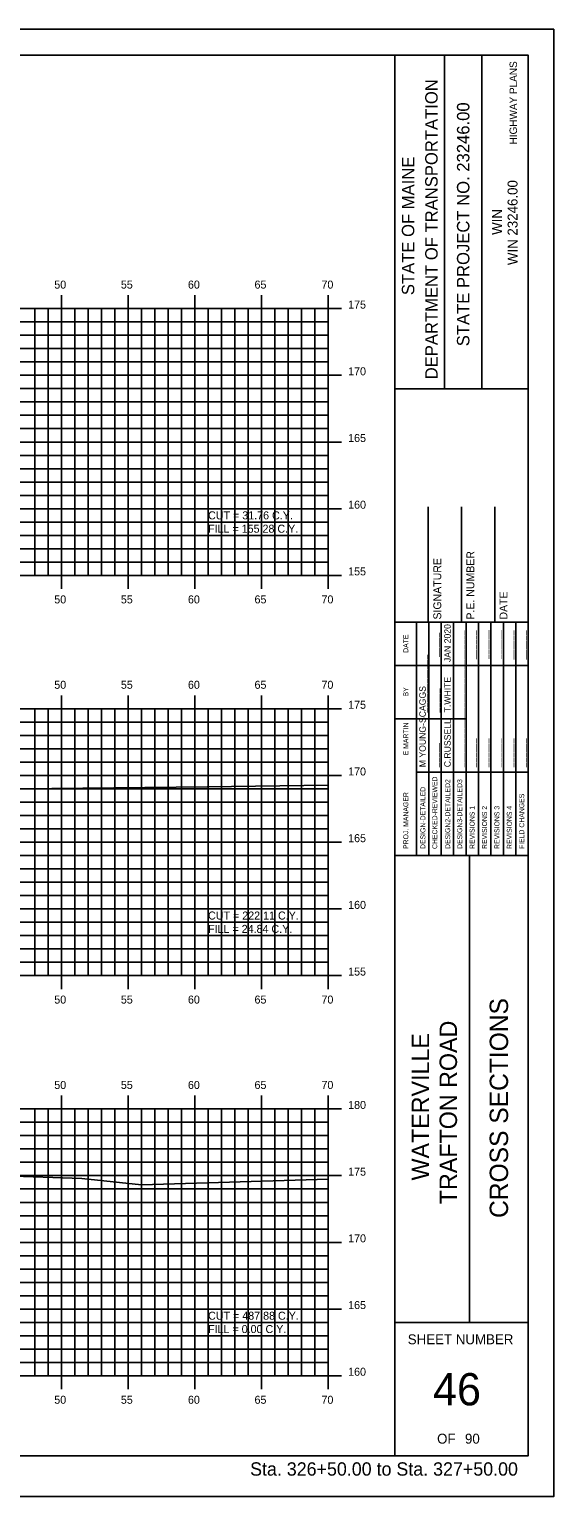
# Model space of a CAD drawing. Extents: x 1140759 to 1140929, y 608981 to 609091.
# Drawn here: x 1140889.6 to 1140928.9, y 608981.3 to 609091.3 of the extents above; entities that cross this region are included whole.
import ezdxf

# ---------------------------------------------------------------- set-up
doc = ezdxf.new("R2010")
doc.units = 0
for name, color, linetype in [('BORDER', 7, 'Continuous'), ('D_Text_Standard', 7, 'Continuous'), ('H_V ANNOTATION', 7, 'Continuous'), ('HIGHWAY_TITLE', 7, 'Continuous'), ('MAJOR', 7, 'Continuous'), ('MINOR', 7, 'Continuous'), ('PLOT BOUNDARY', 7, 'Continuous'), ('S_Roadway_Centerline', 7, 'Continuous')]:
    doc.layers.add(name, color=color, linetype=linetype)

msp = doc.modelspace()

# ---------------------------------------------------------------- linework, layer by layer
at = {"layer": 'BORDER'}
for p, q in [((1140917, 608984.34), (1140917, 609089.34)), ((1140920.73, 609064.33), (1140920.73, 609089.33)), ((1140923.52, 609064.33), (1140923.52, 609089.33)), ((1140917, 609064.33), (1140927, 609064.33)), ((1140919.5, 609046.84), (1140919.5, 609055.49)), ((1140922, 609046.84), (1140922, 609055.49)), ((1140924.5, 609046.84), (1140924.5, 609055.49)), ((1140917, 609046.84), (1140927, 609046.84)), ((1140917, 609029.34), (1140927, 609029.34)), ((1140922.59, 608994.34), (1140922.59, 609029.34)), ((1140917, 608994.34), (1140927, 608994.34))]:
    msp.add_line(p, q, dxfattribs=at)
msp.add_lwpolyline([(1140767, 608984.34), (1140927, 608984.34), (1140927, 609089.34), (1140767, 609089.34)], close=True, dxfattribs=at)
for points in [[(1140918.62, 609043.59), (1140918.62, 609046.84)], [(1140918.62, 609029.34), (1140918.62, 609046.13)], [(1140919.55, 609029.34), (1140919.55, 609046.84)], [(1140920.48, 609046.84), (1140920.48, 609029.34)], [(1140921.41, 609029.34), (1140921.41, 609046.84)], [(1140922.34, 609029.34), (1140922.34, 609046.84)], [(1140923.28, 609029.34), (1140923.28, 609046.84)], [(1140924.21, 609029.34), (1140924.21, 609046.84)], [(1140925.14, 609029.34), (1140925.14, 609046.84)], [(1140926.07, 609029.34), (1140926.07, 609046.84)], [(1140917, 609043.59), (1140927, 609043.59)], [(1140917, 609039.59), (1140918.62, 609039.59)], [(1140918.62, 609039.59), (1140922.34, 609039.59)], [(1140918.62, 609035.59), (1140927, 609035.59)]]:
    msp.add_lwpolyline(points, dxfattribs=at)
at = {"layer": 'MAJOR'}
for p, q in [((1140892, 609071.34), (1140892, 609070.34)), ((1140897, 609071.34), (1140897, 609070.34)), ((1140902, 609071.34), (1140902, 609070.34)), ((1140907, 609071.34), (1140907, 609070.34)), ((1140912, 609071.34), (1140912, 609070.34)), ((1140772, 609070.34), (1140912, 609070.34)), ((1140772, 609070.34), (1140912, 609070.34)), ((1140892, 609050.34), (1140892, 609070.34)), ((1140897, 609050.34), (1140897, 609070.34)), ((1140902, 609050.34), (1140902, 609070.34)), ((1140907, 609050.34), (1140907, 609070.34)), ((1140913, 609070.34), (1140911, 609070.34)), ((1140912, 609050.34), (1140912, 609070.34)), ((1140912, 609050.34), (1140912, 609070.34)), ((1140772, 609065.34), (1140912, 609065.34)), ((1140913, 609065.34), (1140911, 609065.34)), ((1140772, 609060.34), (1140912, 609060.34)), ((1140913, 609060.34), (1140911, 609060.34)), ((1140772, 609055.34), (1140912, 609055.34)), ((1140913, 609055.34), (1140911, 609055.34)), ((1140772, 609050.34), (1140912, 609050.34)), ((1140772, 609050.34), (1140912, 609050.34)), ((1140892, 609049.33), (1140892, 609050.34)), ((1140897, 609049.33), (1140897, 609050.34)), ((1140902, 609049.33), (1140902, 609050.34)), ((1140907, 609049.33), (1140907, 609050.34)), ((1140913, 609050.34), (1140911, 609050.34)), ((1140912, 609049.33), (1140912, 609050.34)), ((1140772, 609040.34), (1140912, 609040.34)), ((1140772, 609040.34), (1140912, 609040.34)), ((1140892, 609041.34), (1140892, 609040.34)), ((1140892, 609020.34), (1140892, 609040.34)), ((1140897, 609041.34), (1140897, 609040.34)), ((1140897, 609020.34), (1140897, 609040.34)), ((1140902, 609041.34), (1140902, 609040.34)), ((1140902, 609020.34), (1140902, 609040.34)), ((1140907, 609041.34), (1140907, 609040.34)), ((1140907, 609020.34), (1140907, 609040.34)), ((1140913, 609040.34), (1140911, 609040.34)), ((1140912, 609041.34), (1140912, 609040.34)), ((1140912, 609020.34), (1140912, 609040.34)), ((1140912, 609020.34), (1140912, 609040.34)), ((1140772, 609035.34), (1140912, 609035.34)), ((1140913, 609035.34), (1140911, 609035.34)), ((1140772, 609030.34), (1140912, 609030.34)), ((1140913, 609030.34), (1140911, 609030.34)), ((1140772, 609025.34), (1140912, 609025.34)), ((1140913, 609025.34), (1140911, 609025.34)), ((1140772, 609020.34), (1140912, 609020.34)), ((1140772, 609020.34), (1140912, 609020.34)), ((1140892, 609019.33), (1140892, 609020.34)), ((1140897, 609019.33), (1140897, 609020.34)), ((1140902, 609019.33), (1140902, 609020.34)), ((1140907, 609019.33), (1140907, 609020.34)), ((1140913, 609020.34), (1140911, 609020.34)), ((1140912, 609019.33), (1140912, 609020.34)), ((1140892, 609011.34), (1140892, 609010.34)), ((1140897, 609011.34), (1140897, 609010.34)), ((1140902, 609011.34), (1140902, 609010.34)), ((1140907, 609011.34), (1140907, 609010.34)), ((1140912, 609011.34), (1140912, 609010.34)), ((1140772, 609010.34), (1140912, 609010.34)), ((1140772, 609010.34), (1140912, 609010.34)), ((1140892, 608990.34), (1140892, 609010.34)), ((1140897, 608990.34), (1140897, 609010.34)), ((1140902, 608990.34), (1140902, 609010.34)), ((1140907, 608990.34), (1140907, 609010.34)), ((1140913, 609010.34), (1140911, 609010.34)), ((1140912, 608990.34), (1140912, 609010.34)), ((1140912, 608990.34), (1140912, 609010.34)), ((1140772, 609005.34), (1140912, 609005.34)), ((1140913, 609005.34), (1140911, 609005.34)), ((1140772, 609000.34), (1140912, 609000.34)), ((1140913, 609000.34), (1140911, 609000.34)), ((1140772, 608995.34), (1140912, 608995.34)), ((1140913, 608995.34), (1140911, 608995.34)), ((1140772, 608990.34), (1140912, 608990.34)), ((1140772, 608990.34), (1140912, 608990.34)), ((1140892, 608989.33), (1140892, 608990.34)), ((1140897, 608989.33), (1140897, 608990.34)), ((1140902, 608989.33), (1140902, 608990.34)), ((1140907, 608989.33), (1140907, 608990.34)), ((1140913, 608990.34), (1140911, 608990.34)), ((1140912, 608989.33), (1140912, 608990.34))]:
    msp.add_line(p, q, dxfattribs=at)
at = {"layer": 'MINOR'}
for p, q in [((1140890, 609050.34), (1140890, 609070.34)), ((1140891, 609050.34), (1140891, 609070.34)), ((1140893, 609050.34), (1140893, 609070.34)), ((1140894, 609050.34), (1140894, 609070.34)), ((1140895, 609050.34), (1140895, 609070.34)), ((1140896, 609050.34), (1140896, 609070.34)), ((1140898, 609050.34), (1140898, 609070.34)), ((1140899, 609050.34), (1140899, 609070.34)), ((1140900, 609050.34), (1140900, 609070.34)), ((1140901, 609050.34), (1140901, 609070.34)), ((1140903, 609050.34), (1140903, 609070.34)), ((1140904, 609050.34), (1140904, 609070.34)), ((1140905, 609050.34), (1140905, 609070.34)), ((1140906, 609050.34), (1140906, 609070.34)), ((1140908, 609050.34), (1140908, 609070.34)), ((1140909, 609050.34), (1140909, 609070.34)), ((1140910, 609050.34), (1140910, 609070.34)), ((1140911, 609050.34), (1140911, 609070.34)), ((1140772, 609069.34), (1140912, 609069.34)), ((1140912, 609069.34), (1140911, 609069.34)), ((1140772, 609068.34), (1140912, 609068.34)), ((1140912, 609068.34), (1140911, 609068.34)), ((1140772, 609067.34), (1140912, 609067.34)), ((1140912, 609067.34), (1140911, 609067.34)), ((1140772, 609066.34), (1140912, 609066.34)), ((1140912, 609066.34), (1140911, 609066.34)), ((1140772, 609064.34), (1140912, 609064.34)), ((1140912, 609064.34), (1140911, 609064.34)), ((1140772, 609063.34), (1140912, 609063.34)), ((1140772, 609062.34), (1140912, 609062.34)), ((1140912, 609063.34), (1140911, 609063.34)), ((1140912, 609062.34), (1140911, 609062.34)), ((1140772, 609061.34), (1140912, 609061.34)), ((1140912, 609061.34), (1140911, 609061.34)), ((1140772, 609059.34), (1140912, 609059.34)), ((1140912, 609059.34), (1140911, 609059.34)), ((1140772, 609058.34), (1140912, 609058.34)), ((1140912, 609058.34), (1140911, 609058.34)), ((1140772, 609057.34), (1140912, 609057.34)), ((1140912, 609057.34), (1140911, 609057.34)), ((1140772, 609056.34), (1140912, 609056.34)), ((1140912, 609056.34), (1140911, 609056.34)), ((1140772, 609054.34), (1140912, 609054.34)), ((1140912, 609054.34), (1140911, 609054.34)), ((1140772, 609053.34), (1140912, 609053.34)), ((1140912, 609053.34), (1140911, 609053.34)), ((1140772, 609052.34), (1140912, 609052.34)), ((1140772, 609051.34), (1140912, 609051.34)), ((1140912, 609052.34), (1140911, 609052.34)), ((1140912, 609051.34), (1140911, 609051.34)), ((1140890, 609020.34), (1140890, 609040.34)), ((1140891, 609020.34), (1140891, 609040.34)), ((1140893, 609020.34), (1140893, 609040.34)), ((1140894, 609020.34), (1140894, 609040.34)), ((1140895, 609020.34), (1140895, 609040.34)), ((1140896, 609020.34), (1140896, 609040.34)), ((1140898, 609020.34), (1140898, 609040.34)), ((1140899, 609020.34), (1140899, 609040.34)), ((1140900, 609020.34), (1140900, 609040.34)), ((1140901, 609020.34), (1140901, 609040.34)), ((1140903, 609020.34), (1140903, 609040.34)), ((1140904, 609020.34), (1140904, 609040.34)), ((1140905, 609020.34), (1140905, 609040.34)), ((1140906, 609020.34), (1140906, 609040.34)), ((1140908, 609020.34), (1140908, 609040.34)), ((1140909, 609020.34), (1140909, 609040.34)), ((1140910, 609020.34), (1140910, 609040.34)), ((1140911, 609020.34), (1140911, 609040.34)), ((1140772, 609039.34), (1140912, 609039.34)), ((1140912, 609039.34), (1140911, 609039.34)), ((1140772, 609038.34), (1140912, 609038.34)), ((1140912, 609038.34), (1140911, 609038.34)), ((1140772, 609037.34), (1140912, 609037.34)), ((1140912, 609037.34), (1140911, 609037.34)), ((1140772, 609036.34), (1140912, 609036.34)), ((1140912, 609036.34), (1140911, 609036.34)), ((1140772, 609034.34), (1140912, 609034.34)), ((1140912, 609034.34), (1140911, 609034.34)), ((1140772, 609033.34), (1140912, 609033.34)), ((1140912, 609033.34), (1140911, 609033.34)), ((1140772, 609032.34), (1140912, 609032.34)), ((1140912, 609032.34), (1140911, 609032.34)), ((1140772, 609031.34), (1140912, 609031.34)), ((1140912, 609031.34), (1140911, 609031.34)), ((1140772, 609029.34), (1140912, 609029.34)), ((1140912, 609029.34), (1140911, 609029.34)), ((1140772, 609028.34), (1140912, 609028.34)), ((1140912, 609028.34), (1140911, 609028.34)), ((1140772, 609027.34), (1140912, 609027.34)), ((1140912, 609027.34), (1140911, 609027.34)), ((1140772, 609026.34), (1140912, 609026.34)), ((1140912, 609026.34), (1140911, 609026.34)), ((1140772, 609024.34), (1140912, 609024.34)), ((1140912, 609024.34), (1140911, 609024.34)), ((1140772, 609023.34), (1140912, 609023.34)), ((1140912, 609023.34), (1140911, 609023.34)), ((1140772, 609022.34), (1140912, 609022.34)), ((1140912, 609022.34), (1140911, 609022.34)), ((1140772, 609021.34), (1140912, 609021.34)), ((1140912, 609021.34), (1140911, 609021.34)), ((1140890, 608990.34), (1140890, 609010.34)), ((1140891, 608990.34), (1140891, 609010.34)), ((1140893, 608990.34), (1140893, 609010.34)), ((1140894, 608990.34), (1140894, 609010.34)), ((1140895, 608990.34), (1140895, 609010.34)), ((1140896, 608990.34), (1140896, 609010.34)), ((1140898, 608990.34), (1140898, 609010.34)), ((1140899, 608990.34), (1140899, 609010.34)), ((1140900, 608990.34), (1140900, 609010.34)), ((1140901, 608990.34), (1140901, 609010.34)), ((1140903, 608990.34), (1140903, 609010.34)), ((1140904, 608990.34), (1140904, 609010.34)), ((1140905, 608990.34), (1140905, 609010.34)), ((1140906, 608990.34), (1140906, 609010.34)), ((1140908, 608990.34), (1140908, 609010.34)), ((1140909, 608990.34), (1140909, 609010.34)), ((1140910, 608990.34), (1140910, 609010.34)), ((1140911, 608990.34), (1140911, 609010.34)), ((1140772, 609009.34), (1140912, 609009.34)), ((1140912, 609009.34), (1140911, 609009.34)), ((1140772, 609008.34), (1140912, 609008.34)), ((1140772, 609007.34), (1140912, 609007.34)), ((1140912, 609008.34), (1140911, 609008.34)), ((1140912, 609007.34), (1140911, 609007.34)), ((1140772, 609006.34), (1140912, 609006.34)), ((1140912, 609006.34), (1140911, 609006.34)), ((1140772, 609004.34), (1140912, 609004.34)), ((1140912, 609004.34), (1140911, 609004.34)), ((1140772, 609003.34), (1140912, 609003.34)), ((1140912, 609003.34), (1140911, 609003.34)), ((1140772, 609002.34), (1140912, 609002.34)), ((1140912, 609002.34), (1140911, 609002.34)), ((1140772, 609001.34), (1140912, 609001.34)), ((1140912, 609001.34), (1140911, 609001.34)), ((1140772, 608999.34), (1140912, 608999.34)), ((1140912, 608999.34), (1140911, 608999.34)), ((1140772, 608998.34), (1140912, 608998.34)), ((1140912, 608998.34), (1140911, 608998.34)), ((1140772, 608997.34), (1140912, 608997.34)), ((1140772, 608996.34), (1140912, 608996.34)), ((1140912, 608997.34), (1140911, 608997.34)), ((1140912, 608996.34), (1140911, 608996.34)), ((1140772, 608994.34), (1140912, 608994.34)), ((1140912, 608994.34), (1140911, 608994.34)), ((1140772, 608993.34), (1140912, 608993.34)), ((1140912, 608993.34), (1140911, 608993.34)), ((1140772, 608992.34), (1140912, 608992.34)), ((1140912, 608992.34), (1140911, 608992.34)), ((1140772, 608991.34), (1140912, 608991.34)), ((1140912, 608991.34), (1140911, 608991.34))]:
    msp.add_line(p, q, dxfattribs=at)
at = {"layer": 'PLOT BOUNDARY'}
msp.add_lwpolyline([(1140758.91, 608981.28), (1140928.91, 608981.28), (1140928.91, 609091.28), (1140758.91, 609091.28)], close=True, dxfattribs=at)
at = {"layer": 'S_Roadway_Centerline'}
for points in [[(1140801.49, 609031.61), (1140807.51, 609031.55), (1140817.11, 609031.61), (1140818.75, 609031.2), (1140823.24, 609030.01), (1140825.61, 609030.43), (1140826.98, 609030.64), (1140828.29, 609030.75), (1140830.09, 609030.94), (1140836.66, 609031.15), (1140841.08, 609031.28), (1140845.13, 609031.05), (1140851.8, 609030.84), (1140853.5, 609030.73), (1140854.75, 609030.63), (1140856.27, 609030.18), (1140858.92, 609029.53), (1140863.58, 609031.53), (1140867.62, 609033.83), (1140881.85, 609034.18), (1140886.58, 609034.31), (1140902.94, 609034.49), (1140912, 609034.62)], [(1140801.75, 608998.98), (1140814.31, 609000.71), (1140815.79, 609000.7), (1140816.99, 609000.42), (1140823.48, 608999.02), (1140825.83, 608999.37), (1140826.87, 608999.63), (1140828, 608999.7), (1140830.23, 608999.9), (1140837.67, 609000.12), (1140841.07, 609000.15), (1140848.11, 608999.75), (1140851.53, 608999.69), (1140853.66, 608999.52), (1140854.65, 608999.44), (1140857.22, 608998.68), (1140858.18, 608998.42), (1140865.51, 609002.59), (1140868.09, 609003.78), (1140874.07, 609004.3), (1140887.7, 609005.32), (1140893.53, 609005.12), (1140898, 609004.66), (1140912, 609005.07)]]:
    msp.add_lwpolyline(points, dxfattribs=at)

# ---------------------------------------------------------------- texts
at = {"layer": 'BORDER'}
for s, height, p in [('DEPARTMENT OF TRANSPORTATION', 0.9318, (1140920.21, 609065.04)), ('STATE PROJECT NO. 23246.00', 0.9318, (1140922.59, 609067.52)), ('STATE OF MAINE', 0.9318, (1140918.46, 609071.35)), ('WIN 23246.00', 0.7453, (1140926.2, 609073.6)), ('WIN', 0.745, (1140925.04, 609075.87)), ('SIGNATURE', 0.591, (1140920.48, 609047.03)), ('P.E. NUMBER', 0.5906, (1140922.96, 609047.03)), ('DATE', 0.591, (1140925.44, 609047.03)), ('DATE', 0.371, (1140918.01, 609044.54)), ('_____', 0.485, (1140920.22, 609044.24)), ('JAN 2020', 0.485, (1140921.19, 609043.84)), ('______', 0.485, (1140922.08, 609044.06)), ('______', 0.485, (1140923.01, 609044.06)), ('______', 0.485, (1140923.95, 609044.07)), ('______', 0.485, (1140924.88, 609044.07)), ('______', 0.485, (1140925.81, 609044.04)), ('______', 0.485, (1140926.74, 609044.04)), ('____________', 0.4845, (1140919.32, 609040.07)), ('____________', 0.4845, (1140922.08, 609040.07)), ('T.WHITE', 0.485, (1140921.19, 609040.07)), ('BY', 0.371, (1140918.01, 609041.27)), ('M YOUNG-SCAGGS', 0.4845, (1140919.32, 609035.96)), ('_____', 0.485, (1140920.26, 609040.07)), ('C.RUSSELL', 0.485, (1140921.19, 609035.96)), ('____________', 0.4845, (1140922.08, 609035.96)), ('E MARTIN', 0.373, (1140918.01, 609036.85)), ('______', 0.485, (1140923.01, 609035.96)), ('______', 0.485, (1140923.95, 609035.96)), ('______', 0.485, (1140924.88, 609035.96)), ('______', 0.485, (1140925.81, 609035.96)), ('______', 0.485, (1140926.74, 609035.96)), ('_____', 0.485, (1140920.22, 609035.96)), ('CHECKED-REVIEWED', 0.3727, (1140920.18, 609029.83)), ('DESIGN2-DETAILED2', 0.3727, (1140921.15, 609029.83)), ('DESIGN3-DETAILED3', 0.3727, (1140922.05, 609029.83)), ('PROJ. MANAGER', 0.3727, (1140918.01, 609029.83)), ('DESIGN-DETAILED', 0.3727, (1140919.29, 609029.83)), ('FIELD CHANGES', 0.3727, (1140926.7, 609029.83)), ('REVISIONS 1', 0.3727, (1140922.98, 609029.83)), ('REVISIONS 2', 0.3727, (1140923.91, 609029.83)), ('REVISIONS 3', 0.3727, (1140924.84, 609029.83)), ('REVISIONS 4', 0.3727, (1140925.77, 609029.83)), ('CROSS SECTIONS', 1.3779, (1140925.49, 609002.17))]:
    msp.add_text(s, height=height, rotation=90, dxfattribs=at).set_placement(p)
for s, height, p in [('SHEET NUMBER', 0.7453, (1140917.97, 608992.7)), ('46', 2.419, (1140919.86, 608988.12)), ('OF', 0.745, (1140920.17, 608985.25)), ('90', 0.745, (1140922.26, 608985.25))]:
    msp.add_text(s, height=height, dxfattribs=at).set_placement(p)
at = {"layer": 'D_Text_Standard'}
for s, p in [('CUT = 31.76 C.Y.', (1140903, 609054.54)), ('FILL = 155.28 C.Y.', (1140903, 609053.54)), ('CUT = 222.11 C.Y.', (1140903, 609024.54)), ('FILL = 24.84 C.Y.', (1140903, 609023.54)), ('CUT = 487.88 C.Y.', (1140903, 608994.54)), ('FILL = 0.00 C.Y.', (1140903, 608993.54))]:
    msp.add_text(s, height=0.6, dxfattribs=at).set_placement(p)
at = {"layer": 'H_V ANNOTATION'}
for s, height, p in [('50', 0.6, (1140891.47, 609071.84)), ('55', 0.6, (1140896.46, 609071.84)), ('60', 0.6, (1140901.49, 609071.84)), ('65', 0.6, (1140906.48, 609071.84)), ('70', 0.6, (1140911.5, 609071.84)), ('175', 0.6, (1140913.5, 609070.34)), ('170', 0.6, (1140913.5, 609065.34)), ('165', 0.6, (1140913.5, 609060.34)), ('160', 0.6, (1140913.5, 609055.34)), ('155', 0.6, (1140913.5, 609050.34)), ('50', 0.6, (1140891.47, 609048.24)), ('55', 0.6, (1140896.46, 609048.24)), ('60', 0.6, (1140901.49, 609048.24)), ('65', 0.6, (1140906.48, 609048.24)), ('70', 0.6, (1140911.5, 609048.24)), ('50', 0.6, (1140891.47, 609041.84)), ('55', 0.6, (1140896.46, 609041.84)), ('60', 0.6, (1140901.49, 609041.84)), ('65', 0.6, (1140906.48, 609041.84)), ('70', 0.6, (1140911.5, 609041.84)), ('175', 0.6, (1140913.5, 609040.34)), ('170', 0.6, (1140913.5, 609035.34)), ('165', 0.6, (1140913.5, 609030.34)), ('160', 0.6, (1140913.5, 609025.34)), ('155', 0.6, (1140913.5, 609020.34)), ('50', 0.6, (1140891.47, 609018.24)), ('55', 0.6, (1140896.46, 609018.24)), ('60', 0.6, (1140901.49, 609018.24)), ('65', 0.6, (1140906.48, 609018.24)), ('70', 0.6, (1140911.5, 609018.24)), ('50', 0.6, (1140891.47, 609011.84)), ('55', 0.6, (1140896.46, 609011.84)), ('60', 0.6, (1140901.49, 609011.84)), ('65', 0.6, (1140906.48, 609011.84)), ('70', 0.6, (1140911.5, 609011.84)), ('180', 0.6, (1140913.5, 609010.34)), ('175', 0.6, (1140913.5, 609005.34)), ('170', 0.6, (1140913.5, 609000.34)), ('165', 0.6, (1140913.5, 608995.34)), ('160', 0.6, (1140913.5, 608990.34)), ('50', 0.6, (1140891.47, 608988.24)), ('55', 0.6, (1140896.46, 608988.24)), ('60', 0.6, (1140901.49, 608988.24)), ('65', 0.6, (1140906.48, 608988.24)), ('70', 0.6, (1140911.5, 608988.24)), ('Sta. 326+50.00 to Sta. 327+50.00', 1.0002, (1140906.15, 608982.85))]:
    msp.add_text(s, height=height, dxfattribs=at).set_placement(p)
at = {"layer": 'HIGHWAY_TITLE'}
for s, height, p in [('HIGHWAY PLANS', 0.559, (1140926.16, 609082.65)), ('TRAFTON ROAD', 1.3043, (1140921.66, 609003.2)), ('WATERVILLE', 1.304, (1140919.57, 609004.98))]:
    msp.add_text(s, height=height, rotation=90, dxfattribs=at).set_placement(p)

doc.saveas('drawing.dxf')
